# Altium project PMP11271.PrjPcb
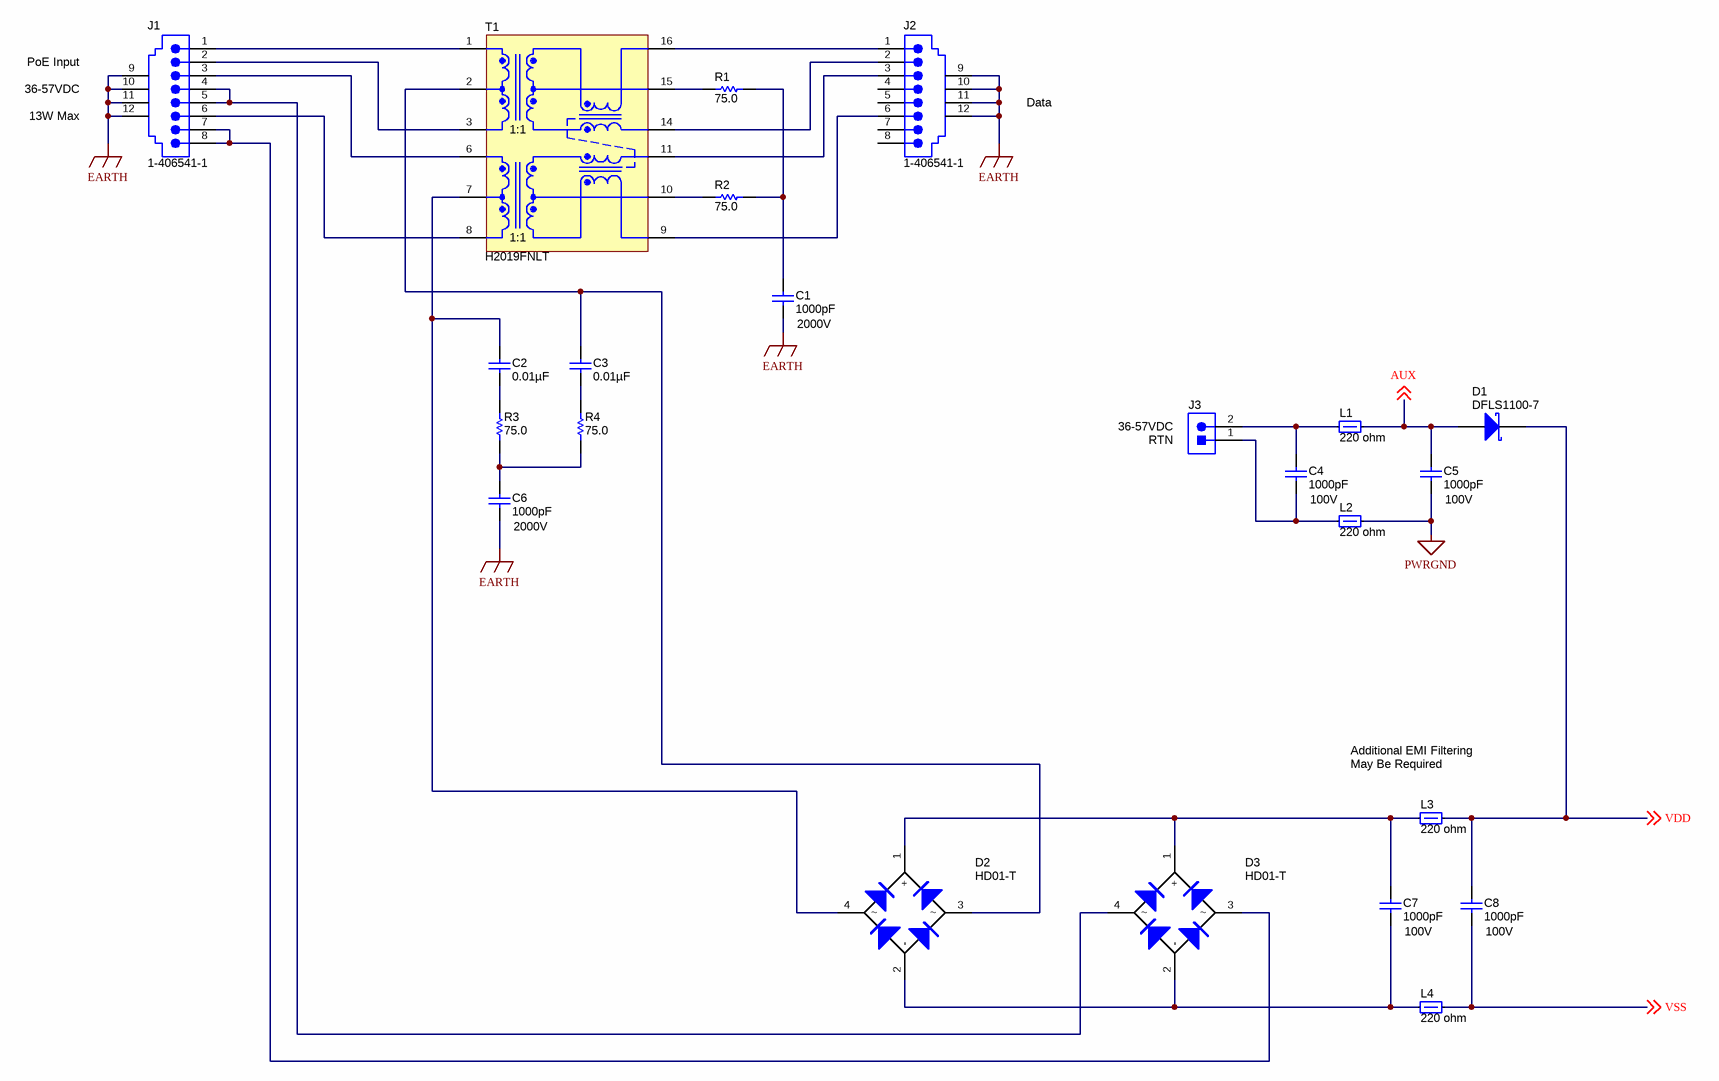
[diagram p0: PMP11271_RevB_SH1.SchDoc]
TID: N/A; TechSupport: N/A; SCH_Rev: B; PRJ_Title: Small, High Efficiency Class 3 PoE Converter; PRJ_Number: PMP11271; PRJ_Engineer: D Strasser; PRJ_Customer: Public Release; PCB_Rev: B; PCB_Layout: N/A; EVM_Orderable: N/A; CopyrightYear: 2015
2 sheets, 97 parts. Net scope: global (net labels, ports and power ports of the same name join across sheets).
Board file: PMP11271_RevA.PcbDoc
Sheets:
  PMP11271_RevB_SH1.SchDoc
  PMP11271_RevB_SH2.SchDoc

## Sheet PMP11271_RevB_SH1.SchDoc: PoE/AUX Input
size 431 x 279 mm; Date: Not shown in title block; ApprovedBy: Not shown in title block; CheckedBy: Not shown in title block; Author: Not shown in title block; CompanyName: Not shown in title block; DrawnBy: D Strasser; Engineer: Not shown in title block; Organization: Not shown in title block; Address1: Not shown in title block; Address2: Not shown in title block; Address3: Not shown in title block; Address4: Not shown in title block; DocumentNumber: 1; Revision: Use project parameter SCH_Rev; SheetNumber: 1; SheetTotal: 2; PageSetup: Record=PageOptions¦CenterHorizontal=True¦CenterVertical=True¦PrintScale=1.00¦XCorrection=1.00¦YCorrection=1.00¦PrintKind=0¦BorderSize=5000000¦LeftOffset=0¦BottomOffset=0¦Orientation=2¦PaperLength=1000¦PaperWidth=1000¦Scale=100¦PaperSource=15¦PrintQuality=600¦MediaType=1¦DitherType=10¦PaperKind=Letter¦PrintScaleMode=1

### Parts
C1  ValueDisplayed: 1000pF  Value2: 2000V  [1812]  (hidden comment: 1812GC102KA1)
C2  ValueDisplayed: 0.01µF  [0603]  (hidden comment: C1608X7R2A103K)
C3  ValueDisplayed: 0.01µF  [0603]  (hidden comment: C1608X7R2A103K)
C4  ValueDisplayed: 1000pF  Value2: 100V  [0603]  (hidden comment: C1608X7R2A102K)
C5  ValueDisplayed: 1000pF  Value2: 100V  [0603]  (hidden comment: C1608X7R2A102K)
C6  ValueDisplayed: 1000pF  Value2: 2000V  [1812]  (hidden comment: 1812GC102KA1)
C7  ValueDisplayed: 1000pF  Value2: 100V  [0603]  (hidden comment: C1608X7R2A102K)
C8  ValueDisplayed: 1000pF  Value2: 100V  [0603]  (hidden comment: C1608X7R2A102K)
D1  DFLS1100-7  [powerDI123]
D2  HD01-T  [MiniDIP]
D3  HD01-T  [MiniDIP]
J1  1-406541-1  [TEC_1-406541-1]
J2  1-406541-1  [TEC_1-406541-1]
J3  ED555/2DS  [TERM_BLK_ED555-2DS]  (value not drawn)
L1  value 220 ohm  [0603]  (hidden comment: MPZ1608S221A)
L2  value 220 ohm  [0603]  (hidden comment: MPZ1608S221A)
L3  value 220 ohm  [0603]  (hidden comment: MPZ1608S221A)
L4  value 220 ohm  [0603]  (hidden comment: MPZ1608S221A)
R1  value 75.0  [0603]  (hidden comment: CRCW060375R0FKEA)
R2  value 75.0  [0603]  (hidden comment: CRCW060375R0FKEA)
R3  value 75.0  [0603]  (hidden comment: CRCW060375R0FKEA)
R4  value 75.0  [0603]  (hidden comment: CRCW060375R0FKEA)
T1  H2019FNLT  [PULSE_H2019FNL]

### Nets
EARTH: C1.2 C6.2 J1.9 J1.10 J1.11 J1.12 J2.9 J2.10 J2.11 J2.12
PWRGND: C5.2 L2.2
AUX: C5.1 D1.2(A) L1.2 ; off-sheet AUX
VDD: C8.1 D1.1(K) L3.2 ; off-sheet VDD
VSS: C8.2 L4.2 ; off-sheet VSS
NetC1_1: C1.1 R1.2 R2.2
NetC2_1: C2.1 D2.4 T1.7(RCT)
NetC2_2: C2.2 R3.2
NetC3_1: C3.1 D2.3 T1.2(TCT)
NetC3_2: C3.2 R4.2
NetC4_1: C4.1 J3.2 L1.1
NetC4_2: C4.2 J3.1 L2.1
NetC6_1: C6.1 R3.1 R4.1
NetC7_1: C7.1 D2.1(+) D3.1(+) L3.1
NetC7_2: C7.2 D2.2(-) D3.2(-) L4.1
NetD3_3: D3.3 J1.7 J1.8
NetD3_4: D3.4 J1.4 J1.5
NetJ1_1: J1.1 T1.1(TD+)
NetJ1_2: J1.2 T1.3(TD-)
NetJ1_3: J1.3 T1.6(RD+)
NetJ1_6: J1.6 T1.8(RD-)
NetJ2_1: J2.1 T1.16(TX+)
NetJ2_2: J2.2 T1.14(TX-)
NetJ2_3: J2.3 T1.11(RX+)
NetJ2_6: J2.6 T1.9(RX-)
NetR1_1: R1.1 T1.15(TXCT)
NetR2_1: R2.1 T1.10(RXCT)

Not connected (* = marked no-connect by the designer): J2 4 5 7 8

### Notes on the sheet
- PoE Input
- 36-57VDC
- 13W Max
- Data
- (near J3) 36-57VDC
- (near J3) RTN
- Additional EMI Filtering
- (near L3) May Be Required

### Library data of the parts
C1 C6 = 1812GC102KA1: CAP, CERM, 1000pF, 2000V, +/-10%, X7R, 1812; Manufacturer: AVX; Polarized: N; CompType: Capacitor; U/M: EA; Cap_F: 0.000000001; Tolerance_%: 10; Value1: Unknown; VDC_V: 2000; TaMin_C: -55; TaMax_C: 125
C2 C3 = C1608X7R2A103K: CAP, CERM, 0.01uF, 100V, +/-10%, X7R, 0603; Manufacturer: TDK; Polarized: N; CompType: Capacitor; U/M: EA; Cap_F: 0.00000001; Tolerance_%: 10; ESR_Ohm: 0.0661; Value1: 0.0661 ohm; VDC_V: 100; TaMin_C: -55; TaMax_C: 125
C4 C5 C7 C8 = C1608X7R2A102K: CAP, CERM, 1000pF, 100V, +/-10%, X7R, 0603; Manufacturer: TDK; Polarized: N; CompType: Capacitor; U/M: EA; Cap_F: 0.000000001; Tolerance_%: 10; ESR_Ohm: 0.2494; Value1: 0.2494 ohm; VDC_V: 100; TaMin_C: -55; TaMax_C: 125
D1 = DFLS1100-7: Diode, Schottky, 100 V, 1 A, PowerDI123; Manufacturer: Diodes Inc.; U/M: EA; Vf_V: 0.77; Value: 100V; Value1: 1A; Value2: 0.77V; Io_A: 1; Vr_V: 100; TJmax_C: 175; RJC_CperW: 7
D2 D3 = HD01-T: Diode, Switching-Bridge, 100 V, 0.8 A, MiniDIP; Manufacturer: Diodes Inc.; U/M: EA; Vf_V: 1; Value: 100V; Value1: 0.8A; Value2: 1V; Io_A: 0.8; Vr_V: 100; TJmax_C: 150
J1 J2 = 1-406541-1: RJ-45, Right Angle, No LED, tab up; Manufacturer: AMP; SymbolCreator: x0208326; CompType: Connector; U/M: EA; Note: updated F/S per request.  Made footprint to max size.  2103-11-27
J3 = ED555/2DS: Terminal Block, 6A, 3.5mm Pitch, 2-Pos, TH; Manufacturer: On-Shore Technology; SymbolCreator: a0412235; CompType: Connector; U/M: EA
L1-L4 = MPZ1608S221A: Ferrite Bead, 220 ohm @ 100 MHz, 2.2 A, 0603; Manufacturer: TDK; Imax_A: 2.2; DCR_ohm: 0.05; Value1: 0.05 ohm; Value2: 2.2A; ZTyp@100MHz_Ohm: 220
R1-R4 = CRCW060375R0FKEA: RES, 75.0 ohm, 1%, 0.1W, 0603; Manufacturer: Vishay-Dale; CompType: Resistor; Res_ohm: 75; Value_Code: 75R0; Tolerance_%: 1; Power_W: 0.1; TempCo: 100 ppm/C; EIA_Code: E96; U/M: EA
T1 = H2019FNLT: Transformer, 350uH, SMT; Manufacturer: Pulse Engineering; SymbolCreator: x0208325; DCR_Ohm: 0.65; U/M: EA

## Sheet PMP11271_RevB_SH2.SchDoc: Isolated Synchronous Flyback Converter
size 431 x 279 mm; Date: Not shown in title block; ApprovedBy: Not shown in title block; CheckedBy: Not shown in title block; Author: Not shown in title block; CompanyName: Not shown in title block; DrawnBy: D Strasser; Engineer: Not shown in title block; Organization: Not shown in title block; Address1: Not shown in title block; Address2: Not shown in title block; Address3: Not shown in title block; Address4: Not shown in title block; DocumentNumber: 2; Revision: Use project parameter SCH_Rev; SheetNumber: 2; SheetTotal: 2; PageSetup: Record=PageOptions¦CenterHorizontal=True¦CenterVertical=True¦PrintScale=1.00¦XCorrection=1.00¦YCorrection=1.00¦PrintKind=0¦BorderSize=5000000¦LeftOffset=0¦BottomOffset=0¦Orientation=2¦PaperLength=1000¦PaperWidth=1000¦Scale=100¦PaperSource=15¦PrintQuality=600¦MediaType=1¦DitherType=10¦PaperKind=Letter¦PrintScaleMode=1
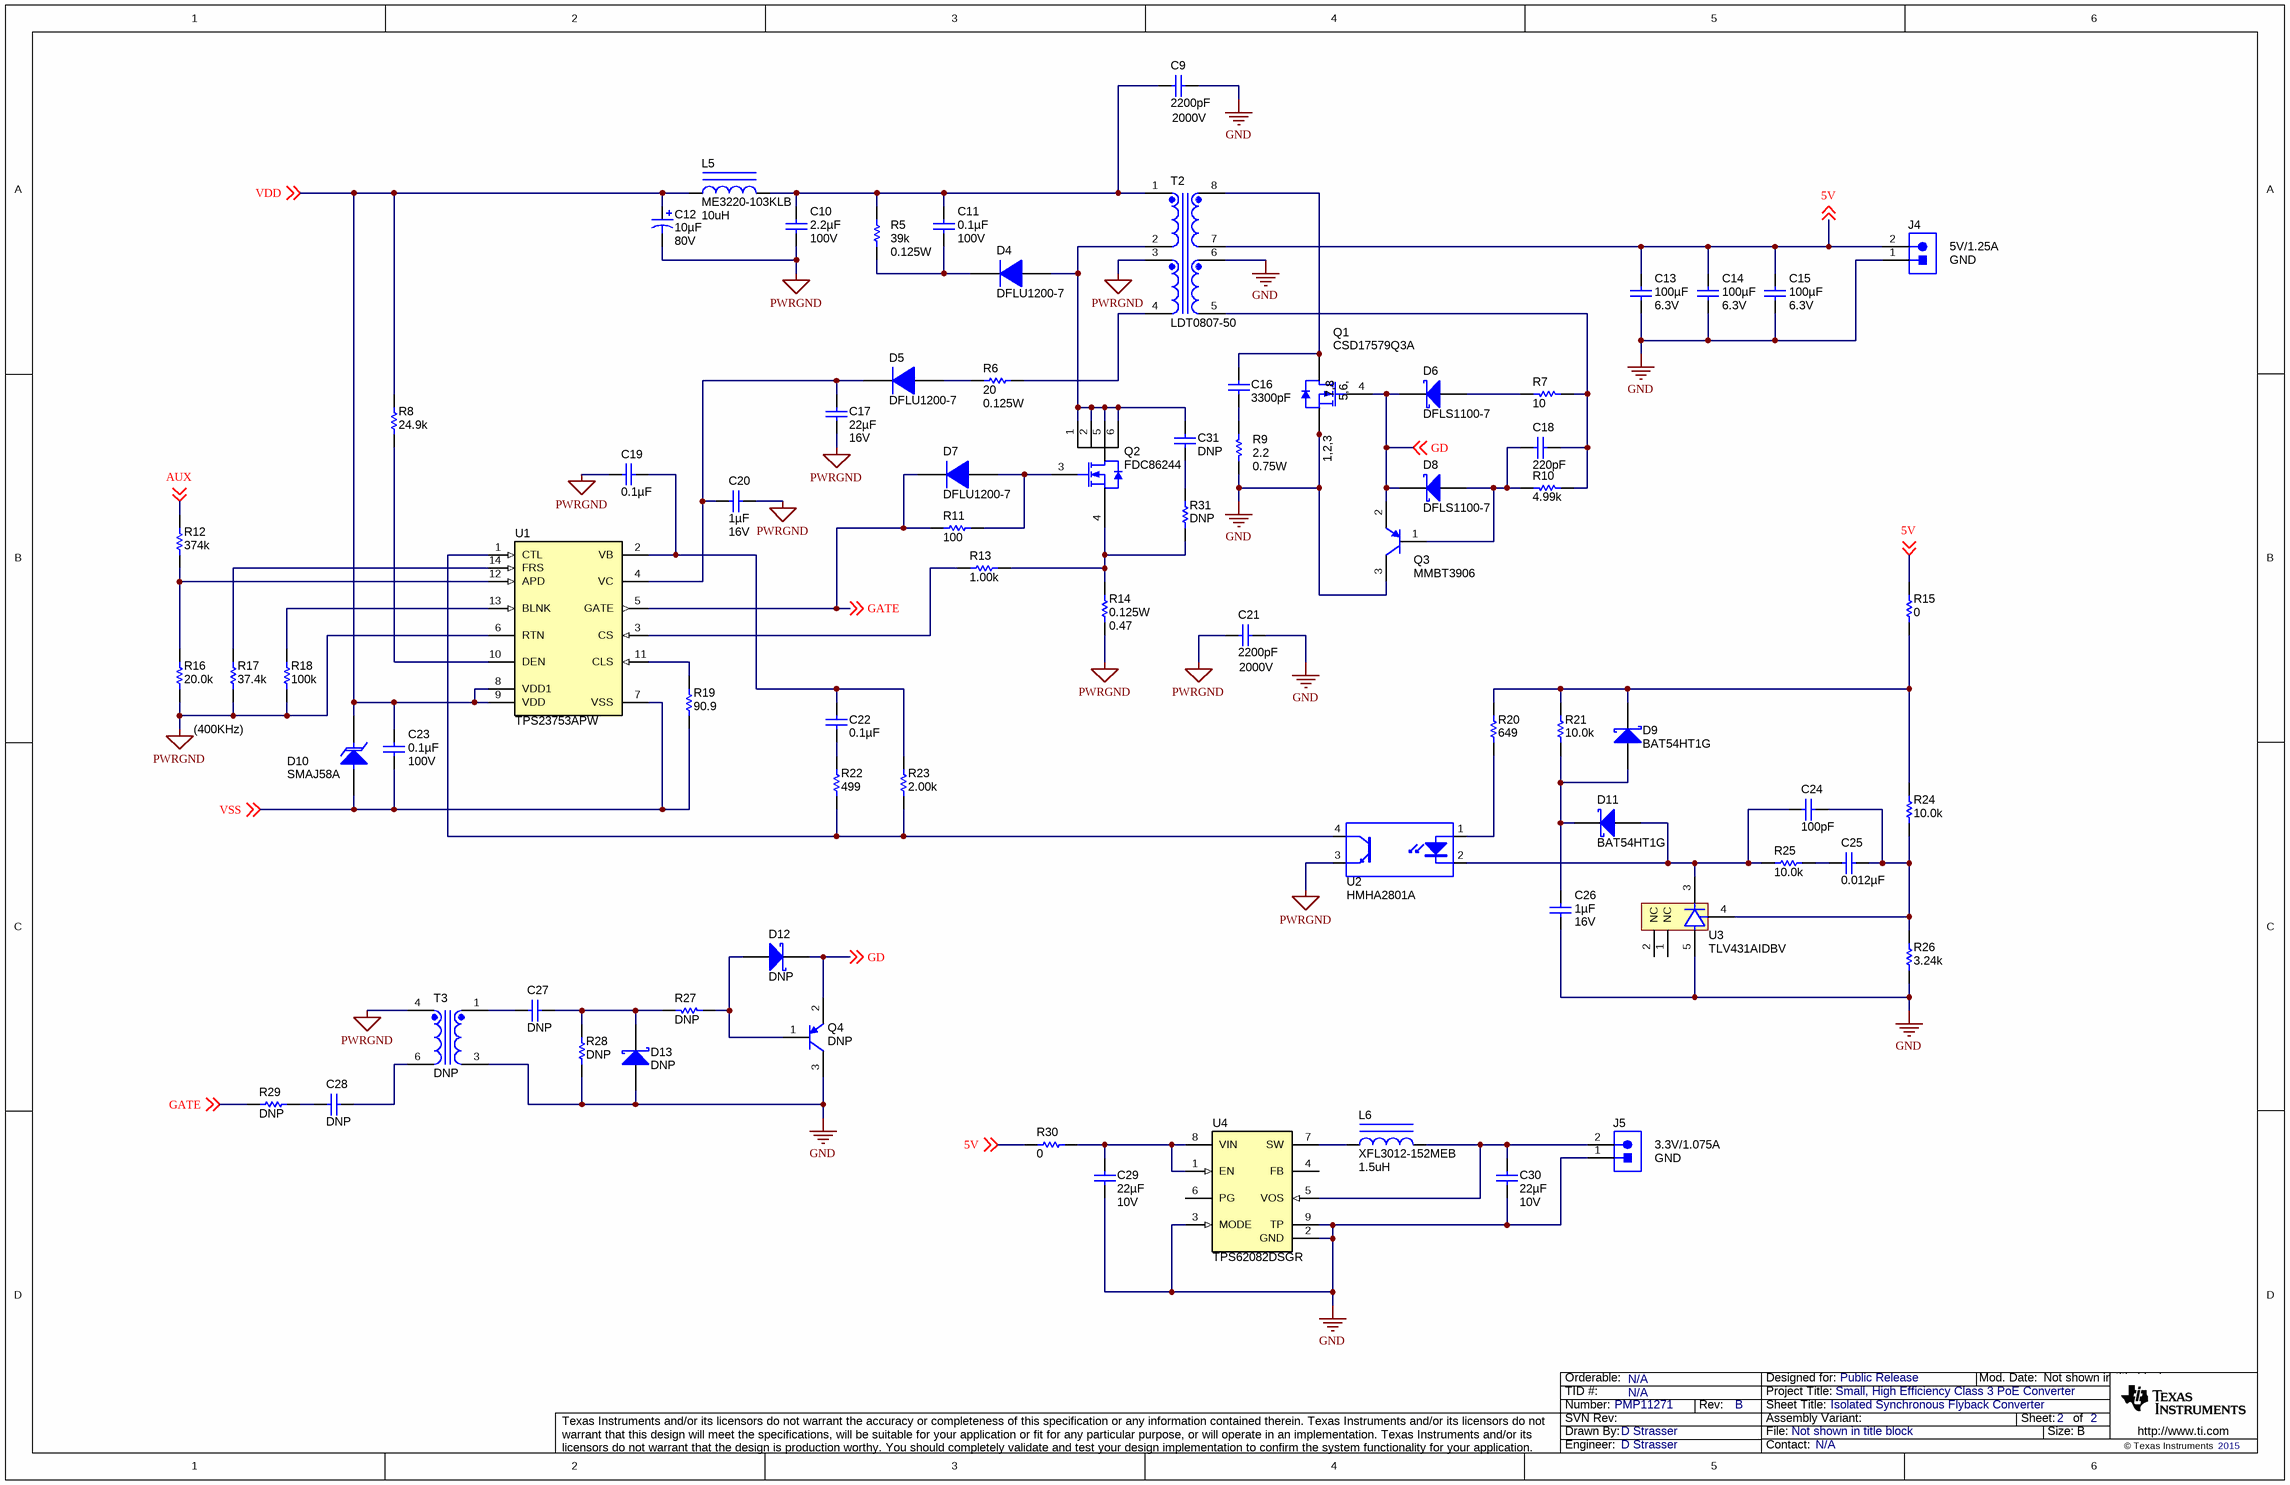
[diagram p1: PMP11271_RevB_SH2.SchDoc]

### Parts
C9  ValueDisplayed: 2200pF  Value2: 2000V  [1812]  (hidden comment: C4532X7R3D222K)
C10  ValueDisplayed: 2.2µF  Value2: 100V  [1210]  (hidden comment: GRM32ER72A225KA35L)
C11  ValueDisplayed: 0.1µF  Value2: 100V  [0805_HV]  (hidden comment: C2012X7R2A104K)
C12  ValueDisplayed: 10µF  Value2: 80V  [SM_RADIAL_E]  (hidden comment: EEE-FK1K100P)
C13  ValueDisplayed: 100µF  Value2: 6.3V  [1210L]  (hidden comment: C3225X5R0J107M)
C14  ValueDisplayed: 100µF  Value2: 6.3V  [1210L]  (hidden comment: C3225X5R0J107M)
C15  ValueDisplayed: 100µF  Value2: 6.3V  [1210L]  (hidden comment: C3225X5R0J107M)
C16  ValueDisplayed: 3300pF  [0603]  (hidden comment: GRM188R71H332KA01D)
C17  ValueDisplayed: 22µF  Value2: 16V  [1210_280]  (hidden comment: C3225X7R1C226K250AC)
C18  ValueDisplayed: 220pF  [0603]  (hidden comment: C1608C0G1H221J)
C19  ValueDisplayed: 0.1µF  [0603]  (hidden comment: C1608X7R1H104K)
C20  ValueDisplayed: 1µF  Value2: 16V  [0603]  (hidden comment: C1608X7R1C105K)
C21  ValueDisplayed: 2200pF  Value2: 2000V  [1812]  (hidden comment: C4532X7R3D222K)
C22  ValueDisplayed: 0.1µF  [0603]  (hidden comment: C1608X7R1H104K)
C23  ValueDisplayed: 0.1µF  Value2: 100V  [0805_HV]  (hidden comment: C2012X7R2A104K)
C24  ValueDisplayed: 100pF  [0402]  (hidden comment: GRM1535C1H101JDD5D)
C25  ValueDisplayed: 0.012µF  [0603]  (hidden comment: GRM188R71E123KA01D)
C26  ValueDisplayed: 1µF  Value2: 16V  [0603]  (hidden comment: C1608X7R1C105K)
C27  value DNP  [0805_HV]  (hidden comment: C2012X7R1E474K)
C28  value DNP  [0805_HV]  (hidden comment: C2012X7R1E474K)
C29  ValueDisplayed: 22µF  Value2: 10V  [0603_100]  (hidden comment: C1608X5R1A226M080AC)
C30  ValueDisplayed: 22µF  Value2: 10V  [0603_100]  (hidden comment: C1608X5R1A226M080AC)
C31  value DNP  [0805_HV]  (hidden comment: GRM21A5C2E680JW01D)
D4  DFLU1200-7  [powerDI123]
D5  DFLU1200-7  [powerDI123]
D6  DFLS1100-7  [powerDI123]
D7  DFLU1200-7  [powerDI123]
D8  DFLS1100-7  [powerDI123]
D9  BAT54HT1G  [sod-323]
D10  SMAJ58A  [SMA]
D11  BAT54HT1G  [sod-323]
D12  value DNP  [powerDI123]  (hidden comment: DFLS1100-7)
D13  value DNP  [powerDI123]  (hidden comment: DFLS1100-7)
J4  ED555/2DS  [TERM_BLK_ED555-2DS]  (value not drawn)
J5  ED555/2DS  [TERM_BLK_ED555-2DS]  (value not drawn)
L5  ME3220-103KLB  value 10uH  [ME3220]
L6  XFL3012-152MEB  value 1.5uH  [XFL3012]
Q1  CSD17579Q3A  [TRANS_NexFET_Q3A]
Q2  FDC86244  [SOT-6]
Q3  MMBT3906  [SOT-23]
Q4  value DNP  [SOT-23]  (hidden comment: MMBT3906)
R5  value 39k  Value2: 0.125W  [0805_HV]  (hidden comment: CRCW080539K0JNEA)
R6  value 20  Value2: 0.125W  [0805_HV]  (hidden comment: CRCW080520R0JNEA)
R7  value 10  [0603]  (hidden comment: CRCW060310R0JNEA)
R8  ValueDisplayed: 24.9k  [0603]  (hidden comment: CRCW060324K9FKEA)
R9  Value2: 0.75W  ValueDisplayed: 2.2  [2010]  (hidden comment: CRCW20102R20JNEF)
R10  value 4.99k  [0603]  (hidden comment: CRCW06034K99FKEA)
R11  ValueDisplayed: 100  [0402]  (hidden comment: CRCW0402100RFKED)
R12  ValueDisplayed: 374k  [0402]  (hidden comment: CRCW0402374KFKED)
R13  ValueDisplayed: 1.00k  [0402]  (hidden comment: CRCW04021K00FKED)
R14  Value2: 0.125W  ValueDisplayed: 0.47  [0805_HV]  (hidden comment: ERJ-6RQFR47V)
R15  ValueDisplayed: 0  [0402]  (hidden comment: ERJ-2GE0R00X)
R16  ValueDisplayed: 20.0k  [0402]  (hidden comment: CRCW040220K0FKED)
R17  ValueDisplayed: 37.4k  [0402]  (hidden comment: CRCW040237K4FKED)
R18  ValueDisplayed: 100k  [0402]  (hidden comment: CRCW0402100KFKED)
R19  value 90.9  [0603]  (hidden comment: CRCW060390R9FKEA)
R20  ValueDisplayed: 649  [0402]  (hidden comment: CRCW0402649RFKED)
R21  ValueDisplayed: 10.0k  [0402]  (hidden comment: CRCW040210K0FKED)
R22  ValueDisplayed: 499  [0402]  (hidden comment: CRCW0402499RFKED)
R23  ValueDisplayed: 2.00k  [0402]  (hidden comment: CRCW04022K00FKED)
R24  ValueDisplayed: 10.0k  [0402]  (hidden comment: CRCW040210K0FKED)
R25  ValueDisplayed: 10.0k  [0402]  (hidden comment: CRCW040210K0FKED)
R26  ValueDisplayed: 3.24k  [0402]  (hidden comment: CRCW04023K24FKED)
R27  value DNP  [0402]  (hidden comment: CRCW040210R0JNED)
R28  value DNP  [0402]  (hidden comment: CRCW040210K0FKED)
R29  value DNP  [0402]  (hidden comment: ERJ-2GE0R00X)
R30  ValueDisplayed: 0  [0603]  (hidden comment: ERJ-3GEY0R00V)
R31  value DNP  [2010]  (hidden comment: CRCW201075R0JNEF)
T2  LDT0807-50  [Linkcom_LDT0807-50]
T3  value DNP  [Wurth_WE-GDT_EP5]  (hidden comment: 760301107)
U1  TPS23753APW  [PW0014A_N]
U2  HMHA2801A  [MFP04A]
U3  TLV431AIDBV  [DBV0005A_N]
U4  TPS62082DSGR  [DSG0008A]

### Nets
GND: C9.1 C13.2 C14.2 C15.2 C21.1 C26.2 C29.2 C30.2 D13.2(A) J4.1 J5.1 Q1.1(S) Q1.2(S) Q1.3(S) Q3.3(C) Q4.3(C) R9.1 R26.1 R28.1 T2.6 T3.3 U3.5(A) U4.2(GND) U4.3(MODE) U4.9(TP)
PWRGND: C10.2 C12.2(-) C17.2 C19.1 C20.2 C21.2 R14.1 R16.1 R17.1 R18.1 T2.3 T3.4 U1.6(RTN) U2.3(E)
5V: C13.1 C14.1 C15.1 J4.2 R15.2 R30.1 T2.7 ; off-sheet 5V
AUX: R12.2 ; off-sheet AUX
GATE: D7.1(K) R11.1 R29.2 U1.5(GATE) ; off-sheet GATE
GD: D6.1(K) D8.1(K) D12.1(K) Q1.4(G) Q3.2(E) Q4.2(E) ; off-sheet GD
VDD: C12.1(+) C23.1 D10.1(K) L5.1 R8.2 U1.8(VDD1) U1.9(VDD) ; off-sheet VDD
VSS: C23.2 D10.2(A) R19.1 U1.7(VSS) ; off-sheet VSS
NetC9_2: C9.2 C10.1 C11.1 L5.2 R5.2 T2.1
NetC11_2: C11.2 D4.1(K) R5.1
NetC16_1: C16.1 Q1.5(D) Q1.6(D) Q1.7(D) Q1.8(D) Q1.9(D) T2.8
NetC16_2: C16.2 R9.2
NetC17_1: C17.1 C20.1 D5.1(K) U1.4(VC)
NetC18_1: C18.1 D8.2(A) Q3.1(B) R10.2
NetC18_2: C18.2 R7.1 R10.1 T2.5
NetC19_2: C19.2 C22.1 R23.2 U1.2(VB)
NetC22_2: C22.2 R22.2
NetC24_1: C24.1 C25.1 R24.1 R26.2 U3.4(REF)
NetC24_2: C24.2 D11.2(A) R25.2 U2.2(K) U3.3(C)
NetC25_2: C25.2 R25.1
NetC26_1: C26.1 D9.2(A) D11.1(K) R21.1
NetC27_1: C27.1 D13.1(K) R27.2 R28.2
NetC27_2: C27.2 T3.1
NetC28_1: C28.1 T3.6
NetC28_2: C28.2 R29.1
NetC29_1: C29.1 R30.2 U4.1(EN) U4.8(VIN)
NetC30_1: C30.1 J5.2 L6.2 U4.5(VOS)
NetC31_1: C31.1 D4.2(A) Q2.1(D) Q2.2(D) Q2.5(D) Q2.6(D) T2.2
NetC31_2: C31.2 R31.2
NetD5_2: D5.2(A) R6.1
NetD6_2: D6.2(A) R7.2
NetD7_2: D7.2(A) Q2.3(G) R11.2
NetD9_1: D9.1(K) R15.1 R20.2 R21.2 R24.2
NetD12_2: D12.2(A) Q4.1(B) R27.1
NetL6_1: L6.1 U4.7(SW)
NetQ2_4: Q2.4(S) R13.1 R14.2 R31.1
NetR6_2: R6.2 T2.4
NetR8_1: R8.1 U1.10(DEN)
NetR12_1: R12.1 R16.2 U1.12(APD)
NetR13_2: R13.2 U1.3(CS)
NetR17_2: R17.2 U1.14(FRS)
NetR18_2: R18.2 U1.13(BLNK)
NetR19_2: R19.2 U1.11(CLS)
NetR20_1: R20.1 U2.1(A)
NetR22_1: R22.1 R23.1 U1.1(CTL) U2.4(C)

Not connected (* = marked no-connect by the designer): U3 1(NC) 2(NC); U4 4(FB) 6(PG)

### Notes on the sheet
- (near J4) 5V/1.25A
- (near J4) GND
- (400KHz)
- (near J5) 3.3V/1.075A
- (near J5) GND

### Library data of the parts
C9 C21 = C4532X7R3D222K: CAP, CERM, 2200pF, 2000V, +/-10%, X7R, 1812; Manufacturer: TDK; Polarized: N; CompType: Capacitor; U/M: EA; Cap_F: 0.0000000022; Tolerance_%: 10; Value1: Unknown; VDC_V: 2000; TaMin_C: -55; TaMax_C: 125
C10 = GRM32ER72A225KA35L: CAP, CERM, 2.2uF, 100V, +/-10%, X7R, 1210; Manufacturer: MuRata; Polarized: N; CompType: Capacitor; U/M: EA; Cap_F: 0.0000022; Tolerance_%: 10; ESR_Ohm: 0.007; Value1: 0.007 ohm; VDC_V: 100; IRMS_A: 4.4; TaMin_C: -55; TaMax_C: 125
C11 C23 = C2012X7R2A104K: CAP, CERM, 0.1uF, 100V, +/-10%, X7R, 0805; Manufacturer: TDK; Polarized: N; CompType: Capacitor; U/M: EA; Cap_F: 0.0000001; Tolerance_%: 10; ESR_Ohm: 0.0158; Value1: 0.0158 ohm; VDC_V: 100; TaMin_C: -55; TaMax_C: 125; Cap_Case: 0805
C12 = EEE-FK1K100P: CAP, AL, 10 µF, 80 V, +/- 20%, 2.4 ohm, SMD; Manufacturer: Panasonic; Polarized: Y; CompType: Capacitor; Value: 10uF; U/M: EA; Cap_F: 0.00001; Tolerance_%: 20; Value1: 2.4 ohm; VDC_V: 80; ESR_ohm: 2.4; IRMS_A: 0.06; TaMin_C: -55; TaMax_C: 105; Cap_Case: E
C13-C15 = C3225X5R0J107M: CAP, CERM, 100uF, 6.3V, +/-20%, X5R, 1210; Manufacturer: TDK; Polarized: N; CompType: Capacitor; U/M: EA; Cap_F: 0.0001; Tolerance_%: 20; ESR_Ohm: 0.002; Value1: 0.002 ohm; VDC_V: 6.3; IRMS_A: 3.5; TaMin_C: -55; TaMax_C: 85; Cap_Case: 1210
C16 = GRM188R71H332KA01D: CAP, CERM, 3300 pF, 50 V, +/- 10%, X7R, 0603; Manufacturer: MuRata; Polarized: N; CompType: Capacitor; Value: 3300pF; U/M: EA; Cap_F: 0.0000000033; Tolerance_%: 10; Value1: Unknown; VDC_V: 50; Value2: 50V; TaMin_C: -55; TaMax_C: 125
C17 = C3225X7R1C226K250AC: CAP, CERM, 22 µF, 16 V, +/- 10%, X7R, 1210; Manufacturer: TDK; Polarized: N; CompType: Capacitor; Value: 22uF; U/M: EA; Cap_F: 0.000022; Tolerance_%: 10; Value1: Unknown; VDC_V: 16; TaMin_C: -55; TaMax_C: 125; Cap_Case: 1210
C18 = C1608C0G1H221J: CAP, CERM, 220 pF, 50 V, +/- 5%, C0G/NP0, 0603; Manufacturer: TDK; Polarized: N; CompType: Capacitor; Value: 220pF; U/M: EA; Cap_F: 0.00000000022; Tolerance_%: 5; ESR_ohm: 0.0831; Value1: 0.0831 ohm; VDC_V: 50; Value2: 50V; TaMin_C: -55; TaMax_C: 125
C19 = C1608X7R1H104K: CAP, CERM, 0.1uF, 50V, +/-10%, X7R, 0603; Manufacturer: TDK; Polarized: N; CompType: Capacitor; U/M: EA; Cap_F: 0.0000001; Tolerance_%: 10; ESR_Ohm: 0.017; Value1: 0.017 ohm; VDC_V: 50; TaMin_C: -55; TaMax_C: 125
C20 C26 = C1608X7R1C105K: CAP, CERM, 1uF, 16V, +/-10%, X7R, 0603; Manufacturer: TDK; Polarized: N; CompType: Capacitor; U/M: EA; Cap_F: 0.000001; Tolerance_%: 10; ESR_Ohm: 0.0057; Value1: 0.0057 ohm; VDC_V: 16; TaMin_C: -55; TaMax_C: 125
C22 = C1608X7R1H104K: CAP, CERM, 0.1 µF, 50 V, +/- 10%, X7R, 0603; Manufacturer: TDK; Polarized: N; CompType: Capacitor; Value: 0.1uF; U/M: EA; Cap_F: 0.0000001; Tolerance_%: 10; ESR_ohm: 0.017; Value1: 0.017 ohm; VDC_V: 50; Value2: 50V; TaMin_C: -55; TaMax_C: 125
C24 = GRM1535C1H101JDD5D: CAP, CERM, 100 pF, 50 V, +/- 5%, C0G/NP0, 0402; Manufacturer: MuRata; Polarized: N; CompType: Capacitor; Value: 100pF; U/M: EA; Cap_F: 0.0000000001; Tolerance_%: 5; Value1: Unknown; VDC_V: 50; Value2: 50V; TaMin_C: -55; TaMax_C: 125
C25 = GRM188R71E123KA01D: CAP, CERM, 0.012 µF, 25 V, +/- 10%, X7R, 0603; Manufacturer: MuRata; Polarized: N; CompType: Capacitor; Value: 0.012uF; U/M: EA; Cap_F: 0.000000012; Tolerance_%: 10; Value1: Unknown; VDC_V: 25; Value2: 25V; TaMin_C: -55; TaMax_C: 125
C27 C28 = C2012X7R1E474K: CAP, CERM, 0.47 µF, 25 V, +/- 10%, X7R, 0805; Manufacturer: TDK; Polarized: N; CompType: Capacitor; ValueDisplayed: 0.47µF; U/M: EA; Cap_F: 0.00000047; Tolerance_%: 10; ESR_ohm: 0.0101; Value1: 0.0101 ohm; VDC_V: 25; Value2: 25V; TaMin_C: -55; TaMax_C: 125; Cap_Case: 0805
C29 C30 = C1608X5R1A226M080AC: CAP, CERM, 22 µF, 10 V, +/- 20%, X5R, 0603; Manufacturer: TDK; Polarized: N; CompType: Capacitor; Value: 22uF; U/M: EA; Cap_F: 0.000022; Tolerance_%: 20; Value1: Unknown; VDC_V: 10; TaMin_C: -55; TaMax_C: 85; Cap_Case: 0603
C31 = GRM21A5C2E680JW01D: CAP, CERM, 68 pF, 250 V, +/- 5%, C0G/NP0, 0805; Manufacturer: MuRata; Polarized: N; CompType: Capacitor; ValueDisplayed: 68pF; U/M: EA; Cap_F: 0.000000000068; Tolerance_%: 5; Value1: Unknown; VDC_V: 250; Value2: 250V; TaMin_C: -55; TaMax_C: 125; Cap_Case: 0805
D4 D5 D7 = DFLU1200-7: Diode, Superfast Rectifier, 200 V, 1 A, PowerDI123; Manufacturer: Diodes Inc.; U/M: EA; Vf_V: 0.98; Value: 200V; Value1: 1A; Value2: 0.98V; Io_A: 1; Vr_V: 200; TJmax_C: 150
D6 D8 = DFLS1100-7: as D1 on sheet PMP11271_RevB_SH1
D9 D11 = BAT54HT1G: Diode, Schottky, 30 V, 0.2 A, SOD-323; Manufacturer: ON Semiconductor; U/M: EA; Vf_V: 0.35; Value: 30V; Value1: 0.2A; Value2: 0.35V; Io_A: 0.2; Vr_V: 30
D10 = SMAJ58A: Diode, TVS, Uni, 58V, 400W, SMA; Manufacturer: Diodes Inc.; U/M: EA; Power_W: 400; Vr_V: 58
D12 D13 = DFLS1100-7: Diode, Schottky, 100 V, 1 A, PowerDI123; Manufacturer: Diodes Inc.; U/M: EA; Vf_V: 0.77; Value1: 1A; Value2: 0.77V; Io_A: 1; Vr_V: 100; TJmax_C: 175; RJC_CperW: 7
J4 J5 = ED555/2DS: as J3 on sheet PMP11271_RevB_SH1
L5 = ME3220-103KLB: Inductor, Drum Core, Ferrite, 10 µH, 0.87 A, 0.43 ohm, SMD; Manufacturer: Coilcraft; Ind_H: 10.0E-6; ValueDisplayed: 10µH; Imax_A: 0.87; Irms: 0.87A @ 40C rise; Isat: 1.1A @ 30% inductance drop; DCR_ohm: 0.43; Value2: 0.87A
L6 = XFL3012-152MEB: Inductor, Shielded, Composite, 1.5 µH, 2.2 A, 0.06 ohm, SMD; Manufacturer: Coilcraft; Ind_H: 1.5E-6; ValueDisplayed: 1.5µH; Imax_A: 2.2; Irms: 2.2A @ 40C rise; Isat: 2.2A @ 30% inductance drop; DCR_ohm: 0.06; Value2: 2.2A
Q1 = CSD17579Q3A: MOSFET, N-CH, 30 V, 20 A, SON 3.3x3.3mm; Manufacturer: Texas Instruments; Alternate Manufacturer: None; Value: 30V; U/M: EA; ChType: N; VdsMax_V: 30; Value1: 0.0142 ohm; Rdson45_ohm: 0.0142; Value2: 5.3 nC; QgTyp_nC: 5.3; Vgs_V: 20
Q2 = FDC86244: MOSFET, N-CH, 150 V, 2.3 A, SuperSOT-6; Manufacturer: Fairchild Semiconductor; Alternate Manufacturer: None; Value: 150V; U/M: EA; ChType: N; VdsMax_V: 150; Value1: ? ohm; Value2: 4.2 nC; QgTyp_nC: 4.2; Vgs_V: 20; IdsMax_A: 2.3; SymbolCreator: x0208325
Q3 = MMBT3906, Fairchild Semiconductor: Transistor, PNP, 40V, 0.2A, SOT-23; CompType: BJT; PNP: 1; NPN: 0; Vceo_V: 40; Vcesat1_V: 0.25; Value: 0.25V; IcRated_A: 0.2; HfeMax: 300; TaMin_C: -55; TaMax_C: 150; U/M: EA
Q4 = MMBT3906, Fairchild Semiconductor: Transistor, PNP, 40V, 0.2A, SOT-23; CompType: BJT; PNP: 1; NPN: 0; Vceo_V: 40; Vcesat1_V: 0.25; IcRated_A: 0.2; HfeMax: 300; TaMin_C: -55; TaMax_C: 150; U/M: EA
R5 = CRCW080539K0JNEA: RES, 39k ohm, 5%, 0.125W, 0805; Manufacturer: Vishay-Dale; CompType: Resistor; Res_ohm: 39000; Value_Code: 39k0; Tolerance_%: 5; Power_W: 0.125; VDC_V: 150; TempCo: 200 ppm/C; EIA_Code: E24; U/M: EA
R6 = CRCW080520R0JNEA: RES, 20 ohm, 5%, 0.125W, 0805; Manufacturer: Vishay-Dale; CompType: Resistor; Value_Code: 20R0; Tolerance_%: 5; Power_W: 0.125; VDC_V: 150; TempCo: 200 ppm/C; EIA_Code: E24; U/M: EA
R7 = CRCW060310R0JNEA: RES, 10 ohm, 5%, 0.1W, 0603; Manufacturer: Vishay-Dale; CompType: Resistor; Value_Code: 10R0; Tolerance_%: 5; Power_W: 0.1; VDC_V: 75; TempCo: 200 ppm/C; EIA_Code: E24; U/M: EA
R8 = CRCW060324K9FKEA: RES, 24.9 k, 1%, 0.1 W, 0603; Manufacturer: Vishay-Dale; CompType: Resistor; Value: 24.9k; Res_ohm: 24900; Value_Code: 24k9; Tolerance_%: 1; Power_W: 0.1; Value2: 0.1W; VDC_V: 75; TempCo: 100 ppm/C; EIA_Code: E96; U/M: EA
R9 = CRCW20102R20JNEF: RES, 2.2, 5%, 0.75 W, 2010; Manufacturer: Vishay-Dale; CompType: Resistor; Value: 2.2; Value_Code: 2R20; Tolerance_%: 5; Power_W: 0.75; VDC_V: 400; TempCo: 200 ppm/C; EIA_Code: E24; U/M: EA
R10 = CRCW06034K99FKEA: RES, 4.99k ohm, 1%, 0.1W, 0603; Manufacturer: Vishay-Dale; CompType: Resistor; Res_ohm: 4990; Value_Code: 4k99; Tolerance_%: 1; Power_W: 0.1; VDC_V: 75; TempCo: 100 ppm/C; EIA_Code: E96; U/M: EA
R11 = CRCW0402100RFKED: RES, 100, 1%, 0.063 W, 0402; Manufacturer: Vishay-Dale; CompType: Resistor; Value: 100; Value_Code: 100R; Tolerance_%: 1; Power_W: 0.063; Value2: 0.063W; VDC_V: 50; TempCo: 100 ppm/C; EIA_Code: E96; U/M: EA
R12 = CRCW0402374KFKED: RES, 374 k, 1%, 0.063 W, 0402; Manufacturer: Vishay-Dale; CompType: Resistor; Value: 374k; Res_ohm: 374000; Tolerance_%: 1; Power_W: 0.063; Value2: 0.063W; VDC_V: 50; TempCo: 100 ppm/C; EIA_Code: E96; U/M: EA
R13 = CRCW04021K00FKED: RES, 1.00 k, 1%, 0.063 W, 0402; Manufacturer: Vishay-Dale; CompType: Resistor; Value: 1.00k; Res_ohm: 1000; Value_Code: 1k00; Tolerance_%: 1; Power_W: 0.063; Value2: 0.063W; VDC_V: 50; TempCo: 100 ppm/C; EIA_Code: E96; U/M: EA
R14 = ERJ-6RQFR47V: RES, 0.47, 1%, 0.125 W, 0805; Manufacturer: Panasonic; CompType: Resistor; Value: 0.47; Value_Code: R470; Tolerance_%: 1; Power_W: 0.125; TempCo: 250 ppm/C; EIA_Code: E96; U/M: EA
R15 = ERJ-2GE0R00X: RES, 0, 5%, 0.063 W, 0402; Manufacturer: Panasonic; CompType: Resistor; Value: 0; Value_Code: 0000; Tolerance_%: 5; Power_W: 0.063; Value2: 0.063W; VDC_V: 50; TempCo: 600 ppm/C; EIA_Code: E24; U/M: EA
R16 = CRCW040220K0FKED: RES, 20.0 k, 1%, 0.063 W, 0402; Manufacturer: Vishay-Dale; CompType: Resistor; Value: 20.0k; Res_ohm: 20000; Value_Code: 20k0; Tolerance_%: 1; Power_W: 0.063; Value2: 0.063W; VDC_V: 50; TempCo: 100 ppm/C; EIA_Code: E96; U/M: EA
R17 = CRCW040237K4FKED: RES, 37.4 k, 1%, 0.063 W, 0402; Manufacturer: Vishay-Dale; CompType: Resistor; Value: 37.4k; Res_ohm: 37400; Value_Code: 37k4; Tolerance_%: 1; Power_W: 0.063; Value2: 0.063W; VDC_V: 50; TempCo: 100 ppm/C; EIA_Code: E96; U/M: EA
R18 = CRCW0402100KFKED: RES, 100 k, 1%, 0.063 W, 0402; Manufacturer: Vishay-Dale; CompType: Resistor; Value: 100k; Res_ohm: 100000; Tolerance_%: 1; Power_W: 0.063; Value2: 0.063W; VDC_V: 50; TempCo: 100 ppm/C; EIA_Code: E96; U/M: EA
R19 = CRCW060390R9FKEA: RES, 90.9 ohm, 1%, 0.1W, 0603; Manufacturer: Vishay-Dale; CompType: Resistor; Value_Code: 90R9; Tolerance_%: 1; Power_W: 0.1; VDC_V: 75; TempCo: 100 ppm/C; EIA_Code: E96; U/M: EA
R20 = CRCW0402649RFKED: RES, 649, 1%, 0.063 W, 0402; Manufacturer: Vishay-Dale; CompType: Resistor; Value: 649; Value_Code: 649R; Tolerance_%: 1; Power_W: 0.063; Value2: 0.063W; VDC_V: 50; TempCo: 100 ppm/C; EIA_Code: E96; U/M: EA
R21 R24 R25 = CRCW040210K0FKED: RES, 10.0 k, 1%, 0.063 W, 0402; Manufacturer: Vishay-Dale; CompType: Resistor; Value: 10.0k; Res_ohm: 10000; Value_Code: 10k0; Tolerance_%: 1; Power_W: 0.063; Value2: 0.063W; VDC_V: 50; TempCo: 100 ppm/C; EIA_Code: E96; U/M: EA
R22 = CRCW0402499RFKED: RES, 499, 1%, 0.063 W, 0402; Manufacturer: Vishay-Dale; CompType: Resistor; Value: 499; Value_Code: 499R; Tolerance_%: 1; Power_W: 0.063; Value2: 0.063W; VDC_V: 50; TempCo: 100 ppm/C; EIA_Code: E96; U/M: EA
R23 = CRCW04022K00FKED: RES, 2.00 k, 1%, 0.063 W, 0402; Manufacturer: Vishay-Dale; CompType: Resistor; Value: 2.00k; Res_ohm: 2000; Value_Code: 2k00; Tolerance_%: 1; Power_W: 0.063; Value2: 0.063W; VDC_V: 50; TempCo: 100 ppm/C; EIA_Code: E96; U/M: EA
R26 = CRCW04023K24FKED: RES, 3.24 k, 1%, 0.063 W, 0402; Manufacturer: Vishay-Dale; CompType: Resistor; Value: 3.24k; Res_ohm: 3240; Value_Code: 3k24; Tolerance_%: 1; Power_W: 0.063; Value2: 0.063W; VDC_V: 50; TempCo: 100 ppm/C; EIA_Code: E96; U/M: EA
R27 = CRCW040210R0JNED: RES, 10, 5%, 0.063 W, 0402; Manufacturer: Vishay-Dale; CompType: Resistor; Res_ohm: 10; Value_Code: 10R0; Tolerance_%: 5; Power_W: 0.063; Value2: 0.063W; VDC_V: 50; TempCo: 200 ppm/C; EIA_Code: E24; U/M: EA
R28 = CRCW040210K0FKED: RES, 10.0 k, 1%, 0.063 W, 0402; Manufacturer: Vishay-Dale; CompType: Resistor; Res_ohm: 10000; Value_Code: 10k0; Tolerance_%: 1; Power_W: 0.063; Value2: 0.063W; VDC_V: 50; TempCo: 100 ppm/C; EIA_Code: E96; U/M: EA; ValueDisplayed: 10.0k
R29 = ERJ-2GE0R00X: RES, 0, 5%, 0.063 W, 0402; Manufacturer: Panasonic; CompType: Resistor; Res_ohm: 0; Value_Code: 0000; Tolerance_%: 5; Power_W: 0.063; Value2: 0.063W; VDC_V: 50; TempCo: 600 ppm/C; EIA_Code: E24; U/M: EA
R30 = ERJ-3GEY0R00V: RES, 0, 5%, 0.1 W, 0603; Manufacturer: Panasonic; CompType: Resistor; Value: 0; Value_Code: 0000; Tolerance_%: 5; Power_W: 0.1; Value2: 0.1W; VDC_V: 50; TempCo: 600 ppm/C; EIA_Code: E24; U/M: EA
R31 = CRCW201075R0JNEF: RES, 75, 5%, 0.75 W, 2010; Manufacturer: Vishay-Dale; CompType: Resistor; ValueDisplayed: 75; Value_Code: 75R0; Tolerance_%: 5; Power_W: 0.75; Value2: 0.75W; VDC_V: 400; TempCo: 200 ppm/C; EIA_Code: E24; U/M: EA
T2 = LDT0807-50: Transformer, 70 uH, SMT; Manufacturer: Linkcom Manufacturing Co.; SymbolCreator: Altium; DCR_Ohm: 0.47; Value: 70 uH; LeakageL: 1 uH; U/M: EA
T3 = 760301107: Transformer, Gate Drive, 650 uH, SMT; Manufacturer: Wurth Elektronik; SymbolCreator: a0412235; DCR_Ohm: 1.2; LeakageL: 2.9 uH; U/M: EA
U1 = TPS23753APW: IEEE 802.3-2005 PoE Interface and Isolated Converter Controller with Enhanced ESD Ride-Through, -40 to 125 degC, 14-pin SOP (PW14), Green (RoHS & no Sb/Br); Manufacturer: Texas Instruments; Alternate PartNumber: Equivalent; Auxiliary Power Rails Supported: 12V-57V; Auxiliary/Local Power Support: Programmable; Duty Cycle(%): 78; Fault Response: Auto Retry; PD Power Level: 13W; PoE Current Limit(Min)(mA): 405; PoE I/F & DC DC Control: TRUE; PoE Inrush Limit(Typ)(mA): 140; PoE Standards Supported: 802.3at type1; rDS(on) per FET(Typ)(mOhms): 700; SubFamily: Powered Device; Switching Frequency: Synchronizable and Programmable; UVLO: Unified
U2 = HMHA2801A: Optocoupler, 3.75kV RMS, SMT; Manufacturer: Fairchild Semiconductor; U/M: EA
U3 = TLV431AIDBV: LOW-VOLTAGE ADJUSTABLE PRECISION SHUNT REGULATOR, DBV0005A; Alternate Manufacturer: None; Manufacturer: Texas Instruments; SymbolCreator: a0411947; CompType: IC; U/M: EA
U4 = TPS62082DSGR: Buck Step Down Regulator with 2.3 to 6 V Input and 3.3 V Output, -40 to 85 degC, 8-Pin WSON (DSG), Green (RoHS & no Sb/Br); Manufacturer: Texas Instruments; Alternate PartNumber: Equivalent; Duty Cycle(Max)(%): 100; Iout(Max)(A): 1.2; Iq(Typ)(mA): 0.006; Rating: Catalog; Regulated Outputs(#): 1; SubFamily: Step-Down Regulator; Switch Current Limit(Typ)(A): 2.4; Vin(Max)(V): 6; Vin(Min)(V): 2.3; Vout(Max)(V): 3.3

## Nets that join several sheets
PWRGND: PMP11271_RevB_SH1 (C5.2 L2.2), PMP11271_RevB_SH2 (14 pins)
AUX: PMP11271_RevB_SH1 (C5.1 D1.2 L1.2), PMP11271_RevB_SH2 (R12.2)
VDD: PMP11271_RevB_SH1 (C8.1 D1.1 L3.2), PMP11271_RevB_SH2 (7 pins)
VSS: PMP11271_RevB_SH1 (C8.2 L4.2), PMP11271_RevB_SH2 (C23.2 D10.2 R19.1 U1.7)

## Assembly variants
001: not fitted FID1 FID2 FID3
